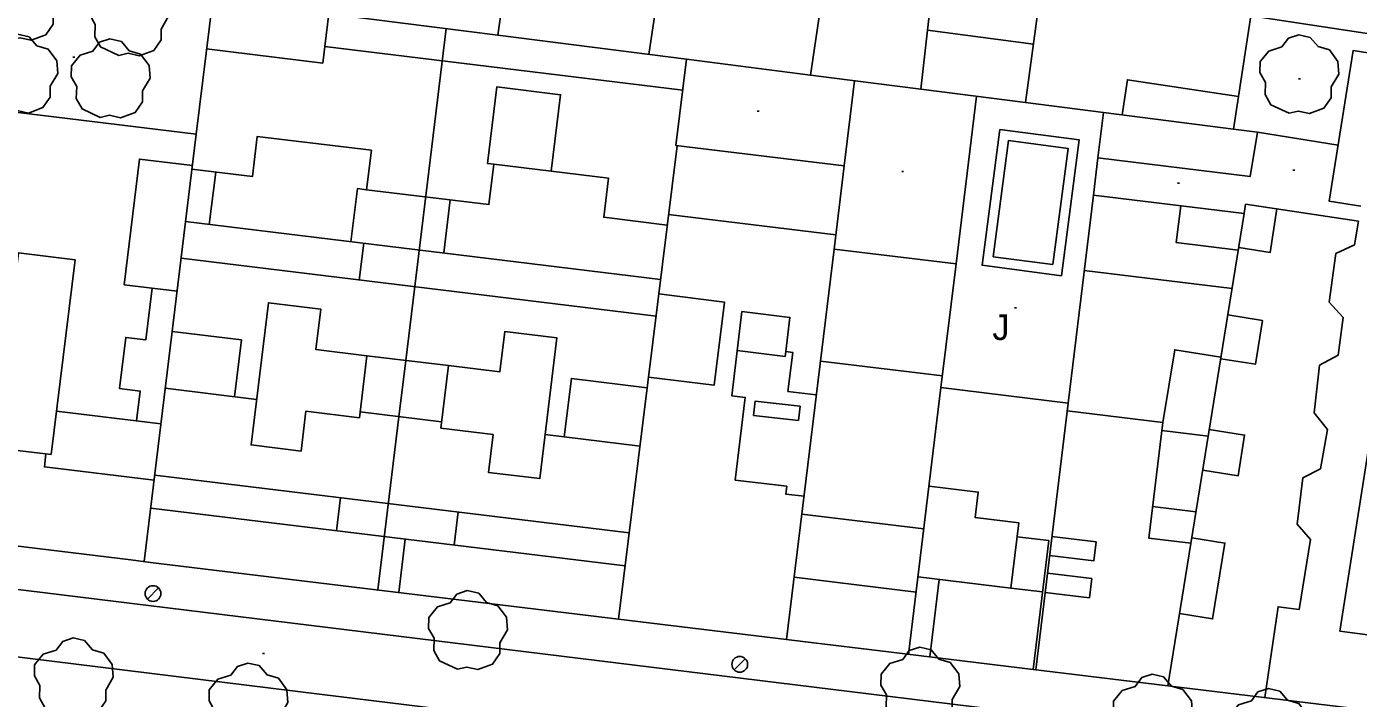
# Model space of a CAD drawing. Extents: x 431390 to 432653, y 4586754 to 4589600.
# Drawn here: x 431880.9 to 431948.5, y 4587093.8 to 4587127.9 of the extents above; entities that cross this region are included whole.
import ezdxf

# ---------------------------------------------------------------- set-up
doc = ezdxf.new("R2010")
doc.units = 0
for name, color, linetype in [('COM_17LS_LN', 7, 'Continuous'), ('CON_01_LN', 7, 'Continuous'), ('CON_01FI_LN', 7, 'Continuous'), ('CON_03_LN', 7, 'Continuous'), ('CON_04_LN', 7, 'Continuous'), ('CON_07_LN', 7, 'Continuous'), ('CON_16_LN', 7, 'Continuous'), ('CON_29_LN', 7, 'Continuous'), ('ENE_06_PT', 7, 'Continuous'), ('ENE_08_LN', 7, 'Continuous'), ('HID_11EX_LN', 7, 'Continuous'), ('HID_11IN_LN', 7, 'Continuous'), ('ORO_03_PT', 7, 'Continuous'), ('TOP_15JA_TX', 7, 'Continuous'), ('VEG_03_PT', 7, 'Continuous')]:
    doc.layers.add(name, color=color, linetype=linetype)

msp = doc.modelspace()

# ---------------------------------------------------------------- linework, layer by layer
at = {"layer": 'COM_17LS_LN'}
for points in [[(431963.914, 4587089.128), (431922.668, 4587094.19), (431896.206, 4587097.438), (431869.183, 4587100.755), (431865.413, 4587101.218)], [(431922.254, 4587090.816), (431895.792, 4587094.064), (431868.769, 4587097.381), (431854.224, 4587099.166), (431849.159, 4587099.733), (431850.662, 4587084.802)]]:
    msp.add_lwpolyline(points, dxfattribs=at)
at = {"layer": 'CON_01_LN'}
for points in [[(431919.477, 4587096.826), (431920.44, 4587096.709), (431924.637, 4587096.199), (431928.383, 4587095.744), (431931.286, 4587095.392), (431964.99, 4587091.3), (431965.794, 4587096.696), (431967.819, 4587110.296), (431973.11, 4587145.83)], [(431852.301, 4587112.393), (431853.06, 4587104.89), (431874.372, 4587102.302), (431886.221, 4587100.863), (431887.225, 4587100.741), (431910.958, 4587097.86)], [(431910.958, 4587097.86), (431919.477, 4587096.826)]]:
    msp.add_lwpolyline(points, dxfattribs=at)
at = {"layer": 'CON_01FI_LN'}
for points in [[(431878.297, 4587142.637), (431879.192, 4587142.508), (431879.415, 4587144.002), (431884.85, 4587143.241), (431884.451, 4587140.57), (431889.723, 4587139.778), (431890.205, 4587143.001), (431892.892, 4587142.599), (431893.014, 4587143.418), (431895.604, 4587143.031), (431894.959, 4587138.716), (431906.205, 4587137.035), (431904.83, 4587127.475), (431890.373, 4587129.321), (431889.537, 4587122.45), (431876.469, 4587124.04), (431874.725, 4587109.67), (431852.301, 4587112.393)], [(431948.468, 4587118.036), (431942.753, 4587118.899), (431942.681, 4587118.435), (431935.032, 4587119.364), (431933.752, 4587108.817), (431927.304, 4587109.6), (431928.066, 4587115.88), (431921.88, 4587116.631), (431922.39, 4587120.842), (431913.865, 4587121.876), (431914.395, 4587126.255), (431920.693, 4587125.451), (431922.832, 4587139.969), (431933.526, 4587138.393), (431931.593, 4587124.06), (431935.541, 4587123.555), (431935.261, 4587121.251), (431942.982, 4587120.313), (431943.345, 4587122.56), (431942.135, 4587122.714), (431943.01, 4587128.46), (431949.032, 4587127.545)], [(431949.798, 4587126.437), (431948.2, 4587126.69), (431946.991, 4587119.05), (431948.588, 4587118.797)]]:
    msp.add_lwpolyline(points, dxfattribs=at)
at = {"layer": 'CON_03_LN'}
for points in [[(431898.752, 4587099.342), (431899.819, 4587108.127), (431900.165, 4587110.984), (431902.209, 4587127.81)], [(431904.83, 4587127.475), (431914.395, 4587126.255)], [(431935.541, 4587123.555), (431942.135, 4587122.714)], [(431886.9, 4587100.78), (431889.537, 4587122.45)], [(431910.958, 4587097.86), (431913.923, 4587121.869)], [(431938.804, 4587094.479), (431942.681, 4587118.435)], [(431919.477, 4587096.826), (431921.88, 4587116.631)], [(431925.662, 4587096.075), (431927.304, 4587109.6)], [(431932.11, 4587095.292), (431933.752, 4587108.817)]]:
    msp.add_lwpolyline(points, dxfattribs=at)
at = {"layer": 'CON_04_LN'}
for points in [[(431916.643, 4587154.271), (431912.491, 4587126.498)], [(431896.06, 4587126.9), (431896.265, 4587128.569)], [(431890.063, 4587126.773), (431895.957, 4587126.056), (431896.06, 4587126.9), (431914.206, 4587124.692)], [(431942.385, 4587124.359), (431936.759, 4587125.216), (431936.488, 4587123.434)], [(431907.545, 4587120.578), (431908.016, 4587124.456), (431904.779, 4587124.85), (431904.308, 4587120.972), (431904.627, 4587120.933)], [(431889.321, 4587120.678), (431892.387, 4587120.305), (431892.634, 4587122.339), (431898.419, 4587121.635), (431898.176, 4587119.639), (431904.378, 4587118.885), (431904.627, 4587120.933), (431910.442, 4587120.226), (431910.2, 4587118.24), (431913.426, 4587117.848)], [(431888.569, 4587114.493), (431885.886, 4587114.819), (431886.662, 4587121.194), (431889.344, 4587120.868)], [(431890.526, 4587120.531), (431890.203, 4587117.876)], [(431897.386, 4587117.002), (431897.714, 4587119.695), (431898.176, 4587119.639)], [(431902.414, 4587119.124), (431902.087, 4587116.43)], [(431921.968, 4587117.358), (431913.493, 4587118.384)], [(431939.461, 4587118.826), (431939.234, 4587116.954), (431942.379, 4587116.572)], [(431944.332, 4587118.661), (431944, 4587116.46), (431942.401, 4587116.702)], [(431888.998, 4587118.023), (431913.086, 4587115.092)], [(431948.468, 4587118.036), (431948.28, 4587116.85), (431947.32, 4587116.4), (431946.99, 4587113.93), (431947.7, 4587113.16), (431947.44, 4587111.24), (431946.5, 4587110.74), (431946.23, 4587108.32), (431946.91, 4587107.47), (431946.54, 4587105.49), (431945.66, 4587105.03), (431945.37, 4587102.67), (431946.04, 4587101.9), (431945.46, 4587098.35), (431944.4, 4587098.49), (431943.727, 4587093.882)], [(431964.14, 4587115.669), (431961.23, 4587095.45), (431947.52, 4587097.26), (431950.736, 4587117.693)], [(431882.19, 4587106.207), (431879.317, 4587106.556), (431880.519, 4587116.434), (431883.392, 4587116.084), (431882.19, 4587106.207)], [(431897.809, 4587115.058), (431898.036, 4587116.923)], [(431888.771, 4587116.158), (431912.856, 4587113.227)], [(431934.569, 4587115.546), (431942.066, 4587114.636)], [(431887.302, 4587114.647), (431886.983, 4587112.023), (431885.968, 4587112.146), (431885.653, 4587109.552), (431886.699, 4587109.425), (431886.516, 4587107.917)], [(431912.995, 4587114.353), (431916.322, 4587113.942), (431915.801, 4587109.721), (431912.474, 4587110.132)], [(431897.814, 4587108.075), (431898.197, 4587111.219), (431895.611, 4587111.534), (431895.86, 4587113.578), (431893.198, 4587113.902), (431892.321, 4587106.695), (431894.854, 4587106.387), (431895.1, 4587108.405), (431897.814, 4587108.075)], [(431920.358, 4587104.09), (431919.433, 4587104.202), (431919.481, 4587104.601), (431916.872, 4587104.917), (431917.38, 4587109.108), (431916.691, 4587109.192), (431917.208, 4587113.456), (431919.646, 4587113.16), (431919.436, 4587111.433), (431919.784, 4587111.391), (431919.543, 4587109.408), (431920.982, 4587109.233)], [(431941.848, 4587113.286), (431943.61, 4587113.001), (431943.251, 4587110.783), (431941.489, 4587111.068)], [(431891.482, 4587109.141), (431891.833, 4587112.025), (431888.32, 4587112.452)], [(431901.936, 4587107.547), (431902.323, 4587110.727), (431904.935, 4587110.409), (431905.183, 4587112.446), (431907.83, 4587112.124), (431906.962, 4587104.987), (431904.355, 4587105.304), (431904.589, 4587107.224), (431901.936, 4587107.547)], [(431902.323, 4587110.727), (431898.197, 4587111.219)], [(431919.436, 4587111.433), (431919.406, 4587111.186), (431916.968, 4587111.48)], [(431921.19, 4587110.948), (431927.376, 4587110.197)], [(431941.502, 4587111.147), (431939.157, 4587111.526), (431938.547, 4587107.833)], [(431887.97, 4587109.569), (431892.602, 4587109.005)], [(431912.407, 4587109.592), (431908.565, 4587110.066), (431908.2, 4587107.107)], [(431882.458, 4587108.411), (431887.75, 4587107.767)], [(431897.85, 4587108.367), (431901.975, 4587107.865)], [(431933.704, 4587108.421), (431938.547, 4587107.833), (431937.836, 4587101.974), (431939.975, 4587101.714)], [(431907.234, 4587107.225), (431912.042, 4587106.64)], [(431938.498, 4587107.43), (431940.854, 4587107.144)], [(431940.909, 4587107.484), (431942.702, 4587107.194), (431942.367, 4587105.124), (431940.574, 4587105.414)], [(431881.917, 4587106.24), (431881.837, 4587105.583), (431887.402, 4587104.908)], [(431887.434, 4587105.171), (431911.499, 4587102.243)], [(431926.698, 4587104.61), (431929.191, 4587104.307), (431929.035, 4587103.018), (431931.248, 4587102.749), (431930.846, 4587099.435), (431926.139, 4587100.006)], [(431887.229, 4587103.486), (431911.291, 4587100.558)], [(431896.851, 4587104.025), (431896.646, 4587102.34)], [(431938.03, 4587103.572), (431940.232, 4587103.305)], [(431902.823, 4587103.299), (431902.618, 4587101.613)], [(431900.142, 4587101.915), (431899.813, 4587099.213)], [(431931.162, 4587102.044), (431932.766, 4587101.849), (431931.971, 4587095.309)], [(431932.931, 4587102.054), (431935.172, 4587101.782), (431935.055, 4587100.822), (431932.814, 4587101.094)], [(431940.019, 4587101.989), (431941.698, 4587101.717), (431941.076, 4587097.873), (431939.397, 4587098.145)], [(431932.705, 4587100.192), (431934.946, 4587099.92), (431934.827, 4587098.937), (431932.586, 4587099.209)], [(431919.86, 4587099.985), (431926.046, 4587099.235)], [(431927.219, 4587099.875), (431926.742, 4587095.943)]]:
    msp.add_lwpolyline(points, dxfattribs=at)
at = {"layer": 'CON_07_LN'}
msp.add_lwpolyline([(431931.593, 4587124.06), (431926.287, 4587124.737), (431926.62, 4587127.73), (431931.993, 4587127.025)], dxfattribs=at)
at = {"layer": 'CON_16_LN'}
for points in [[(431926.62, 4587127.73), (431927.015, 4587131.09)], [(431926.287, 4587124.737), (431920.693, 4587125.451)], [(431922.915, 4587125.167), (431922.39, 4587120.842)], [(431929.098, 4587124.378), (431928.066, 4587115.88)], [(431943.345, 4587122.56), (431947.442, 4587121.899)], [(431935.261, 4587121.251), (431935.032, 4587119.364)]]:
    msp.add_lwpolyline(points, dxfattribs=at)
at = {"layer": 'CON_29_LN'}
for points in [[(431920.248, 4587103.184), (431926.434, 4587102.434)], [(431930.846, 4587099.435), (431932.449, 4587099.241)]]:
    msp.add_lwpolyline(points, dxfattribs=at)
at = {"layer": 'ENE_06_PT'}
for p, q in [((431887.632, 4587099.442), (431887.066, 4587098.876)), ((431917.382, 4587095.852), (431916.816, 4587095.286))]:
    msp.add_line(p, q, dxfattribs=at)
for centre in [(431887.349, 4587099.159), (431917.099, 4587095.569)]:
    msp.add_circle(centre, 0.4, dxfattribs=at)
at = {"layer": 'ENE_08_LN'}
msp.add_lwpolyline([(431920.074, 4587107.927), (431917.8, 4587108.19), (431917.884, 4587108.918), (431920.158, 4587108.655), (431920.074, 4587107.927)], dxfattribs=at)
at = {"layer": 'HID_11EX_LN'}
msp.add_lwpolyline([(431933.411, 4587115.279), (431934.311, 4587122.161), (431930.291, 4587122.687), (431929.391, 4587115.805), (431933.411, 4587115.279)], dxfattribs=at)
at = {"layer": 'HID_11IN_LN'}
msp.add_lwpolyline([(431932.98, 4587115.84), (431933.75, 4587121.73), (431930.722, 4587122.126), (431929.952, 4587116.236), (431932.98, 4587115.84)], dxfattribs=at)
at = {"layer": 'ORO_03_PT'}
for p, q in [((431883.28, 4587126.36), (431883.38, 4587126.36)), ((431945.44, 4587125.26), (431945.54, 4587125.26)), ((431917.99, 4587123.62), (431918.09, 4587123.62)), ((431925.31, 4587120.56), (431925.41, 4587120.56)), ((431945.14, 4587120.63), (431945.24, 4587120.63)), ((431939.29, 4587119.97), (431939.39, 4587119.97)), ((431931.03, 4587113.64), (431931.13, 4587113.64)), ((431892.898, 4587096.125), (431892.998, 4587096.125))]:
    msp.add_line(p, q, dxfattribs=at)
at = {"layer": 'VEG_03_PT'}
for points in [[(431880.134, 4587127.231), (431879.207, 4587127.666), (431878.919, 4587128.187), (431878.942, 4587128.801), (431878.66, 4587129.293), (431878.668, 4587129.856), (431879.109, 4587130.391), (431879.762, 4587130.595), (431880.097, 4587131.046), (431880.623, 4587131.216), (431881.203, 4587131.083), (431881.603, 4587130.617), (431882.177, 4587130.447), (431882.611, 4587129.864), (431882.66, 4587129.222), (431882.277, 4587128.575), (431882.277, 4587128.025), (431881.905, 4587127.491), (431881.166, 4587127.216), (431880.601, 4587127.344), (431880.134, 4587127.231)], [(431885.614, 4587126.441), (431884.687, 4587126.876), (431884.399, 4587127.397), (431884.422, 4587128.011), (431884.14, 4587128.503), (431884.148, 4587129.066), (431884.589, 4587129.601), (431885.242, 4587129.805), (431885.577, 4587130.256), (431886.103, 4587130.426), (431886.683, 4587130.293), (431887.083, 4587129.827), (431887.657, 4587129.657), (431888.091, 4587129.074), (431888.14, 4587128.432), (431887.757, 4587127.785), (431887.757, 4587127.235), (431887.385, 4587126.701), (431886.646, 4587126.426), (431886.081, 4587126.554), (431885.614, 4587126.441)], [(431879.994, 4587123.541), (431879.067, 4587123.976), (431878.779, 4587124.497), (431878.802, 4587125.111), (431878.52, 4587125.603), (431878.528, 4587126.166), (431878.969, 4587126.701), (431879.622, 4587126.905), (431879.957, 4587127.356), (431880.483, 4587127.526), (431881.063, 4587127.393), (431881.463, 4587126.927), (431882.037, 4587126.757), (431882.471, 4587126.174), (431882.52, 4587125.532), (431882.137, 4587124.885), (431882.137, 4587124.335), (431881.765, 4587123.801), (431881.026, 4587123.526), (431880.461, 4587123.654), (431879.994, 4587123.541)], [(431884.674, 4587123.301), (431883.747, 4587123.736), (431883.459, 4587124.257), (431883.482, 4587124.871), (431883.2, 4587125.363), (431883.208, 4587125.926), (431883.649, 4587126.461), (431884.302, 4587126.665), (431884.637, 4587127.116), (431885.163, 4587127.286), (431885.743, 4587127.153), (431886.143, 4587126.687), (431886.717, 4587126.517), (431887.151, 4587125.934), (431887.2, 4587125.292), (431886.817, 4587124.645), (431886.817, 4587124.095), (431886.445, 4587123.561), (431885.706, 4587123.286), (431885.141, 4587123.414), (431884.674, 4587123.301)], [(431944.954, 4587123.511), (431944.027, 4587123.946), (431943.739, 4587124.467), (431943.762, 4587125.081), (431943.48, 4587125.573), (431943.488, 4587126.136), (431943.929, 4587126.671), (431944.582, 4587126.875), (431944.917, 4587127.326), (431945.443, 4587127.496), (431946.023, 4587127.363), (431946.423, 4587126.897), (431946.997, 4587126.727), (431947.431, 4587126.144), (431947.48, 4587125.502), (431947.097, 4587124.855), (431947.097, 4587124.305), (431946.725, 4587123.771), (431945.986, 4587123.496), (431945.421, 4587123.624), (431944.954, 4587123.511)], [(431902.794, 4587095.321), (431901.867, 4587095.756), (431901.579, 4587096.277), (431901.602, 4587096.891), (431901.32, 4587097.383), (431901.328, 4587097.946), (431901.769, 4587098.481), (431902.422, 4587098.685), (431902.757, 4587099.136), (431903.283, 4587099.306), (431903.863, 4587099.173), (431904.263, 4587098.707), (431904.837, 4587098.537), (431905.271, 4587097.954), (431905.32, 4587097.312), (431904.937, 4587096.665), (431904.937, 4587096.115), (431904.565, 4587095.581), (431903.826, 4587095.306), (431903.261, 4587095.434), (431902.794, 4587095.321)], [(431882.804, 4587092.921), (431881.877, 4587093.356), (431881.589, 4587093.877), (431881.612, 4587094.491), (431881.33, 4587094.983), (431881.338, 4587095.546), (431881.779, 4587096.081), (431882.432, 4587096.285), (431882.767, 4587096.736), (431883.293, 4587096.906), (431883.873, 4587096.773), (431884.273, 4587096.307), (431884.847, 4587096.137), (431885.281, 4587095.554), (431885.33, 4587094.912), (431884.947, 4587094.265), (431884.947, 4587093.715), (431884.575, 4587093.181), (431883.836, 4587092.906), (431883.271, 4587093.034), (431882.804, 4587092.921)], [(431925.734, 4587092.451), (431924.807, 4587092.886), (431924.519, 4587093.407), (431924.542, 4587094.021), (431924.26, 4587094.513), (431924.268, 4587095.076), (431924.709, 4587095.611), (431925.362, 4587095.815), (431925.697, 4587096.266), (431926.223, 4587096.436), (431926.803, 4587096.303), (431927.203, 4587095.837), (431927.777, 4587095.667), (431928.211, 4587095.084), (431928.26, 4587094.442), (431927.877, 4587093.795), (431927.877, 4587093.245), (431927.505, 4587092.711), (431926.766, 4587092.436), (431926.201, 4587092.564), (431925.734, 4587092.451)], [(431891.664, 4587091.651), (431890.737, 4587092.086), (431890.449, 4587092.607), (431890.472, 4587093.221), (431890.19, 4587093.713), (431890.198, 4587094.276), (431890.639, 4587094.811), (431891.292, 4587095.015), (431891.627, 4587095.466), (431892.153, 4587095.636), (431892.733, 4587095.503), (431893.133, 4587095.037), (431893.707, 4587094.867), (431894.141, 4587094.284), (431894.19, 4587093.642), (431893.807, 4587092.995), (431893.807, 4587092.445), (431893.435, 4587091.911), (431892.696, 4587091.636), (431892.131, 4587091.764), (431891.664, 4587091.651)], [(431937.524, 4587091.081), (431936.597, 4587091.516), (431936.309, 4587092.037), (431936.332, 4587092.651), (431936.05, 4587093.143), (431936.058, 4587093.706), (431936.499, 4587094.241), (431937.152, 4587094.445), (431937.487, 4587094.896), (431938.013, 4587095.066), (431938.593, 4587094.933), (431938.993, 4587094.467), (431939.567, 4587094.297), (431940.001, 4587093.714), (431940.05, 4587093.072), (431939.667, 4587092.425), (431939.667, 4587091.875), (431939.295, 4587091.341), (431938.556, 4587091.066), (431937.991, 4587091.194), (431937.524, 4587091.081)], [(431943.414, 4587090.361), (431942.487, 4587090.796), (431942.199, 4587091.317), (431942.222, 4587091.931), (431941.94, 4587092.423), (431941.948, 4587092.986), (431942.389, 4587093.521), (431943.042, 4587093.725), (431943.377, 4587094.176), (431943.903, 4587094.346), (431944.483, 4587094.213), (431944.883, 4587093.747), (431945.457, 4587093.577), (431945.891, 4587092.994), (431945.94, 4587092.352), (431945.557, 4587091.705), (431945.557, 4587091.155), (431945.185, 4587090.621), (431944.446, 4587090.346), (431943.881, 4587090.474), (431943.414, 4587090.361)]]:
    msp.add_lwpolyline(points, dxfattribs=at)

# ---------------------------------------------------------------- texts
at = {"layer": 'TOP_15JA_TX'}
msp.add_text('J', height=1.3, dxfattribs=at).set_placement((431929.91, 4587112.015))

doc.saveas('drawing.dxf')
